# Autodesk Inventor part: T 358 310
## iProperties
Created: 2006-01
Part Number: T 358 310
Material: 2.0402.26
Document SubType Name: Modeling
Designer: I.Baliuc
Manufacturer: Standard
Standards Organization: Custom
Description: Hülse
Density: 8.2 g/cm^3
Title: Hülse
Company: Mayer & Müller AG Schaltgeräte
HalbzeugNorm: DIN 1756
Zweck: für Vorkontaktträger
Abmessung: Rd 12 - 18
Author: T.Messerschmitt
Revision Number: 358310
Keywords: 267034
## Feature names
1. Drehung1 [Revolution]
